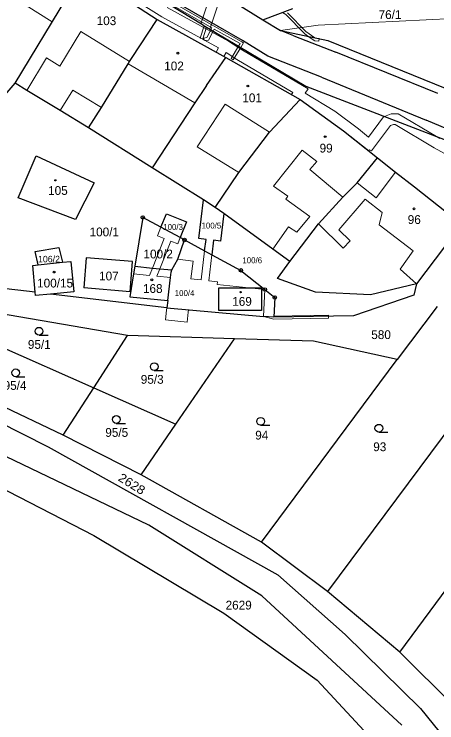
# Model space of a CAD drawing. Extents: x -606517 to -602431, y -1183120 to -1179397.
# Drawn here: x -605326.3 to -605244.5, y -1181147.4 to -1181010.4 of the extents above; entities that cross this region are included whole.
import ezdxf
from ezdxf.enums import TextEntityAlignment as Align

# ---------------------------------------------------------------- set-up
doc = ezdxf.new("R2010")
doc.units = 0
doc.header["$LTSCALE"] = 0.68
for name, color, linetype, lineweight in [('1', 7, 'Continuous', 25), ('13', 7, 'Continuous', 13), ('3', 7, 'Continuous', 25), ('4', 7, 'Continuous', 13), ('5', 7, 'Continuous', 25), ('8', 7, 'Continuous', 25)]:
    doc.layers.add(name, color=color, linetype=linetype, lineweight=lineweight)
doc.layers.add('2', color=7, linetype='Continuous')

msp = doc.modelspace()

# ---------------------------------------------------------------- linework, layer by layer
at = {"layer": '1'}
for p, q in [((-605307.47, -1180993.15), (-605278.18, -1181011.48)), ((-605289.7, -1181012.53), (-605312.8, -1180998.45)), ((-605326.09, -1181023.72), (-605313, -1181002.07)), ((-605313, -1181002.07), (-605298.57, -1181011.41)), ((-605282.12, -1181015.49), (-605296.19, -1181007.32)), ((-605278.18, -1181011.48), (-605272.35, -1181009.31)), ((-605303.57, -1181018.98), (-605298.57, -1181011.41)), ((-605298.57, -1181011.41), (-605285.31, -1181018.79)), ((-605278.18, -1181011.48), (-605274.74, -1181013.56)), ((-605289.7, -1181012.53), (-605269.85, -1181024.33)), ((-605272.13, -1181014.58), (-605274.74, -1181013.56)), ((-605274.74, -1181013.56), (-605265.59, -1181015.49)), ((-605277.19, -1181018.51), (-605282.12, -1181015.49)), ((-605272.13, -1181014.58), (-605264.02, -1181017.75)), ((-605265.59, -1181015.49), (-605242.91, -1181024.7)), ((-605266.78, -1181022.59), (-605277.19, -1181018.51)), ((-605244.28, -1181025.71), (-605264.02, -1181017.75)), ((-605304.2, -1181020.01), (-605303.92, -1181019.55)), ((-605303.92, -1181019.55), (-605303.57, -1181018.98)), ((-605289.08, -1181024.18), (-605285.31, -1181018.79)), ((-605285.31, -1181018.79), (-605270.94, -1181026.88)), ((-605309.38, -1181028.43), (-605304.2, -1181020.01)), ((-605266.78, -1181022.59), (-605246.54, -1181030.86)), ((-605357.02, -1181060.03), (-605326.09, -1181023.72)), ((-605323.82, -1181025.15), (-605326.09, -1181023.72)), ((-605317.36, -1181029.05), (-605323.82, -1181025.15)), ((-605289.08, -1181024.18), (-605291.3, -1181027.55)), ((-605269.85, -1181024.33), (-605225.51, -1181041.42)), ((-605291.3, -1181027.55), (-605299.58, -1181040.1)), ((-605276.84, -1181033.18), (-605270.94, -1181026.88)), ((-605270.94, -1181026.88), (-605262.56, -1181032.95)), ((-605311.91, -1181032.36), (-605317.36, -1181029.05)), ((-605311.91, -1181032.36), (-605309.38, -1181028.43)), ((-605223.86, -1181040.55), (-605246.54, -1181030.86)), ((-605299.58, -1181040.1), (-605311.91, -1181032.36)), ((-605282.8, -1181041.03), (-605276.84, -1181033.18)), ((-605262.56, -1181032.95), (-605255.96, -1181038.18)), ((-605325.5, -1181045.9), (-605322, -1181037.8)), ((-605322, -1181037.8), (-605310.8, -1181043)), ((-605259.92, -1181042.99), (-605255.96, -1181038.18)), ((-605255.96, -1181038.18), (-605252.47, -1181040.91)), ((-605289.64, -1181046.32), (-605299.58, -1181040.1)), ((-605287.36, -1181047.75), (-605282.8, -1181041.03)), ((-605252.47, -1181040.91), (-605248.85, -1181043.75)), ((-605310.8, -1181043), (-605314.4, -1181050.1)), ((-605262.7, -1181045.77), (-605259.92, -1181042.99)), ((-605248.85, -1181043.75), (-605242.6, -1181048.68)), ((-605314.4, -1181050.1), (-605325.5, -1181045.9)), ((-605267.4, -1181050.94), (-605262.7, -1181045.77)), ((-605290.51, -1181053.77), (-605289.64, -1181046.32)), ((-605287.36, -1181047.75), (-605289.64, -1181046.32)), ((-605285.72, -1181048.94), (-605287.36, -1181047.75)), ((-605301.39, -1181049.69), (-605302.91, -1181059.13)), ((-605297.86, -1181051.59), (-605301.39, -1181049.69)), ((-605297.86, -1181051.59), (-605296.81, -1181048.99)), ((-605296.81, -1181048.99), (-605292.92, -1181050.55)), ((-605276.25, -1181055.82), (-605285.72, -1181048.94)), ((-605292.92, -1181050.55), (-605294.14, -1181053.6)), ((-605272.94, -1181058.19), (-605267.4, -1181050.94)), ((-605294.14, -1181053.6), (-605297.86, -1181051.59)), ((-605240.31, -1181051.74), (-605248.45, -1181062.54)), ((-605294.6, -1181057.78), (-605293.3, -1181054.05)), ((-605293.3, -1181054.05), (-605294.14, -1181053.6)), ((-605293.3, -1181054.05), (-605289.41, -1181056.15)), ((-605289.15, -1181053.94), (-605290.51, -1181053.77)), ((-605289.41, -1181056.15), (-605289.15, -1181053.94)), ((-605287.7, -1181054.1), (-605288.02, -1181056.9)), ((-605322.2, -1181056.3), (-605317.6, -1181055.5)), ((-605317.6, -1181055.5), (-605316.9, -1181058.35)), ((-605321.64, -1181058.86), (-605322.2, -1181056.3)), ((-605289.41, -1181056.15), (-605288.02, -1181056.9)), ((-605272.94, -1181058.19), (-605276.25, -1181055.82)), ((-605316.9, -1181058.35), (-605315.31, -1181058.18)), ((-605315.31, -1181058.18), (-605314.71, -1181064.05)), ((-605303.8, -1181064.1), (-605303.4, -1181058.2)), ((-605295.73, -1181059.84), (-605294.6, -1181057.78)), ((-605288.02, -1181056.9), (-605282.4, -1181059.93)), ((-605275.29, -1181061.48), (-605272.94, -1181058.19)), ((-605322.66, -1181058.97), (-605321.64, -1181058.86)), ((-605322.18, -1181064.16), (-605322.66, -1181058.97)), ((-605321.64, -1181058.86), (-605316.9, -1181058.35)), ((-605302.91, -1181059.13), (-605303.15, -1181060.61)), ((-605302.91, -1181059.13), (-605299.5, -1181059.47)), ((-605299.5, -1181059.47), (-605298.09, -1181059.6)), ((-605298.09, -1181059.6), (-605295.73, -1181059.84)), ((-605322.18, -1181064.16), (-605357.02, -1181060.03)), ((-605303.15, -1181060.61), (-605303.86, -1181065.01)), ((-605296.04, -1181061.32), (-605295.92, -1181060.3)), ((-605295.92, -1181060.3), (-605295.73, -1181059.84)), ((-605282.4, -1181059.93), (-605277.77, -1181063.63)), ((-605296.53, -1181065.74), (-605296.04, -1181061.32)), ((-605267.96, -1181064.16), (-605275.29, -1181061.48)), ((-605303.8, -1181064.1), (-605312.8, -1181063.3)), ((-605286.7, -1181063.3), (-605280.85, -1181063.3)), ((-605286.7, -1181067.7), (-605286.7, -1181063.3)), ((-605280.85, -1181063.3), (-605278.4, -1181063.3)), ((-605278.4, -1181063.3), (-605278.4, -1181063.56)), ((-605278.4, -1181063.56), (-605278.4, -1181067.7)), ((-605277.77, -1181063.63), (-605275.85, -1181065.17)), ((-605248.45, -1181062.54), (-605257.33, -1181064.67)), ((-605248.45, -1181062.54), (-605248.94, -1181064.71)), ((-605322.12, -1181064.8), (-605322.18, -1181064.16)), ((-605319.24, -1181064.51), (-605322.12, -1181064.8)), ((-605314.71, -1181064.05), (-605319.24, -1181064.51)), ((-605296.7, -1181067.18), (-605319.24, -1181064.51)), ((-605303.86, -1181065.01), (-605296.53, -1181065.74)), ((-605257.33, -1181064.67), (-605267.96, -1181064.16)), ((-605248.94, -1181064.71), (-605260.6, -1181068.71)), ((-605296.53, -1181065.74), (-605296.7, -1181067.18)), ((-605275.85, -1181065.17), (-605276.05, -1181068.97)), ((-605304.35, -1181072.51), (-605332.24, -1181067.72)), ((-605296.7, -1181067.18), (-605278.05, -1181068.86)), ((-605278.4, -1181067.7), (-605286.7, -1181067.7)), ((-605244.41, -1181066.91), (-605252.17, -1181077.14)), ((-605276.05, -1181068.97), (-605278.05, -1181068.86)), ((-605260.6, -1181068.71), (-605276.05, -1181068.97)), ((-605334.15, -1181072.37), (-605310.87, -1181082.62)), ((-605310.87, -1181082.62), (-605304.35, -1181072.51)), ((-605283.64, -1181073.15), (-605304.35, -1181072.51)), ((-605294.96, -1181089.64), (-605283.64, -1181073.15)), ((-605268.34, -1181073.61), (-605283.64, -1181073.15)), ((-605252.17, -1181077.14), (-605268.34, -1181073.61)), ((-605356.82, -1181075.45), (-605319.69, -1181094.02)), ((-605278.42, -1181112.47), (-605252.17, -1181077.14)), ((-605231.85, -1181076.56), (-605265.64, -1181122.03)), ((-605316.79, -1181091.8), (-605337.96, -1181081.67)), ((-605316.79, -1181091.8), (-605310.87, -1181082.62)), ((-605310.87, -1181082.62), (-605294.96, -1181089.64)), ((-605251.63, -1181133.76), (-605217.59, -1181087.45)), ((-605301.69, -1181099.45), (-605294.96, -1181089.64)), ((-605301.69, -1181099.45), (-605316.79, -1181091.8)), ((-605300.23, -1181109.15), (-605332.19, -1181093.85)), ((-605319.69, -1181094.02), (-605275.27, -1181118.81)), ((-605334.62, -1181098.91), (-605310.86, -1181111.19)), ((-605278.42, -1181112.47), (-605301.69, -1181099.45)), ((-605278.34, -1181122.84), (-605300.23, -1181109.15)), ((-605310.86, -1181111.19), (-605285.73, -1181126.21)), ((-605265.64, -1181122.03), (-605278.42, -1181112.47)), ((-605275.27, -1181118.81), (-605262.26, -1181130.3)), ((-605251.63, -1181133.76), (-605265.64, -1181122.03)), ((-605251.29, -1181147.85), (-605278.34, -1181122.84)), ((-605285.73, -1181126.21), (-605267.62, -1181139.17)), ((-605262.26, -1181130.3), (-605247.67, -1181144.62)), ((-605238.13, -1181147.19), (-605251.63, -1181133.76)), ((-605267.62, -1181139.17), (-605254.57, -1181153.22)), ((-605247.67, -1181144.62), (-605220.34, -1181178.24))]:
    msp.add_line(p, q, dxfattribs=at)
for points in [[(-605285.72, -1181048.94), (-605286.34, -1181054.26), (-605287.7, -1181054.1)], [(-605303.4, -1181058.2), (-605312.3, -1181057.5), (-605312.8, -1181063.3)]]:
    msp.add_lwpolyline(points, dxfattribs=at)
at = {"layer": '13'}
for points in [[(-605299.24, -1181006.56), (-605288, -1181013.05), (-605288.2, -1181013.42), (-605289, -1181014.94), (-605289.58, -1181015.03), (-605289.51, -1181015.52), (-605288.68, -1181015.4), (-605287.77, -1181013.68), (-605287.57, -1181013.29), (-605282.55, -1181016.09), (-605282.86, -1181016.6), (-605284.3, -1181018.98), (-605283.88, -1181019.24), (-605282.43, -1181016.85), (-605281.89, -1181015.96), (-605282.19, -1181015.72), (-605287.55, -1181012.73), (-605298.98, -1181006.12)], [(-605326.18, -1181007.24), (-605318.91, -1181011.85), (-605317.86, -1181010.11)], [(-605304.22, -1181006.8), (-605297.69, -1181010.89), (-605286.73, -1181016.93), (-605287.18, -1181017.75), (-605286.5, -1181018.13), (-605285.71, -1181018.57), (-605285.24, -1181017.82), (-605283.18, -1181019.14), (-605272.33, -1181025.52), (-605272.61, -1181025.94), (-605270.94, -1181026.88), (-605262.56, -1181032.95), (-605257.66, -1181036.83), (-605257.51, -1181036.63), (-605257.12, -1181036.82), (-605253.47, -1181031.94), (-605252.91, -1181031.7), (-605252.56, -1181031.71), (-605244.99, -1181036.22), (-605233.54, -1181042.56)], [(-605243.93, -1181034.46), (-605244.59, -1181034.07), (-605254.63, -1181030.19), (-605254.79, -1181030.26), (-605257.71, -1181034.17), (-605259.64, -1181032.58), (-605264.24, -1181029.17), (-605269.96, -1181025.67), (-605269.41, -1181024.84), (-605282.12, -1181017.38), (-605284.82, -1181015.62), (-605296.65, -1181009.11)], [(-605274.36, -1181010.06), (-605273.72, -1181010.49), (-605270.13, -1181014.16), (-605269.36, -1181014.7), (-605268.09, -1181015.57), (-605267.31, -1181015.62), (-605267.28, -1181015.13), (-605268.09, -1181014.96), (-605269.81, -1181013.78), (-605273.4, -1181010.11)]]:
    msp.add_lwpolyline(points, dxfattribs=at)
for points in [[(-605290.14, -1181012.26), (-605289.7, -1181012.53), (-605288.38, -1181013.31), (-605286.16, -1181006.49), (-605287.9, -1181005.39)], [(-605289.48, -1181012.66), (-605290.26, -1181015.03), (-605289.78, -1181015.19), (-605289.04, -1181012.92)], [(-605254.63, -1181030.19), (-605244.59, -1181034.07), (-605251.98, -1181029.65), (-605253.31, -1181029.64)], [(-605296.96, -1181069.51), (-605292.79, -1181069.96), (-605292.59, -1181067.99), (-605292.55, -1181067.55), (-605296.7, -1181067.18), (-605296.78, -1181067.64)], [(-605276.06, -1181069.37), (-605265.44, -1181069.19), (-605265.45, -1181068.79), (-605265.45, -1181068.59), (-605276.04, -1181068.77), (-605276.05, -1181068.97), (-605278.05, -1181068.86)]]:
    msp.add_lwpolyline(points, close=True, dxfattribs=at)
at = {"layer": '3'}
for p, q in [((-605321.443, -1181072.44), (-605319.693, -1181072.44)), ((-605299.163, -1181079.28), (-605297.413, -1181079.28)), ((-605325.953, -1181080.48), (-605324.203, -1181080.48)), ((-605306.503, -1181089.5), (-605304.753, -1181089.5)), ((-605278.583, -1181089.87), (-605276.833, -1181089.87)), ((-605255.713, -1181091.19), (-605253.963, -1181091.19))]:
    msp.add_line(p, q, dxfattribs=at)
for centre in [(-605321.4429, -1181071.6898), (-605299.1629, -1181078.5298), (-605325.9529, -1181079.7298), (-605306.5029, -1181088.7498), (-605278.5829, -1181089.1198), (-605255.7129, -1181090.4398)]:
    msp.add_circle(centre, 0.75, dxfattribs=at)
at = {"layer": '4'}
for p, q in [((-605236.55, -1181010.99), (-605267.44, -1181012.5)), ((-605267.44, -1181012.5), (-605274.74, -1181013.56)), ((-605313.37, -1181013.77), (-605317.4, -1181020.43)), ((-605303.92, -1181019.55), (-605313.37, -1181013.77)), ((-605320.02, -1181018.85), (-605323.82, -1181025.15)), ((-605317.4, -1181020.43), (-605320.02, -1181018.85)), ((-605291.3, -1181027.55), (-605304.2, -1181020.01)), ((-605314.89, -1181025.06), (-605317.36, -1181029.05)), ((-605309.38, -1181028.43), (-605314.89, -1181025.06)), ((-605285.46, -1181027.78), (-605290.86, -1181036.03)), ((-605278.26, -1181032.3), (-605285.46, -1181027.78)), ((-605276.84, -1181033.18), (-605278.26, -1181032.3)), ((-605290.86, -1181036.03), (-605282.8, -1181041.03)), ((-605270.55, -1181036.7), (-605276.12, -1181043.62)), ((-605267.72, -1181038.85), (-605270.55, -1181036.7)), ((-605269.05, -1181040.45), (-605267.72, -1181038.85)), ((-605262.7, -1181045.77), (-605269.05, -1181040.45)), ((-605256.25, -1181045.93), (-605252.47, -1181040.91)), ((-605259.92, -1181042.99), (-605256.25, -1181045.93)), ((-605276.12, -1181043.62), (-605273.35, -1181045.6)), ((-605273.35, -1181045.6), (-605273.74, -1181046.15)), ((-605273.74, -1181046.15), (-605269.06, -1181049.49)), ((-605258.34, -1181046.13), (-605263.43, -1181052.1)), ((-605255.08, -1181048.77), (-605258.34, -1181046.13)), ((-605269.06, -1181049.49), (-605271.6, -1181052.51)), ((-605255.68, -1181051.13), (-605255.08, -1181048.77)), ((-605262.59, -1181055.62), (-605267.4, -1181050.94)), ((-605249.05, -1181056.16), (-605255.68, -1181051.13)), ((-605298.53, -1181053.24), (-605297.86, -1181051.59)), ((-605273.18, -1181051.5), (-605276.25, -1181055.82)), ((-605271.6, -1181052.51), (-605273.18, -1181051.5)), ((-605263.43, -1181052.1), (-605261.26, -1181054.19)), ((-605299.5, -1181059.47), (-605297.23, -1181053.77)), ((-605297.23, -1181053.77), (-605298.53, -1181053.24)), ((-605294.14, -1181053.6), (-605294.63, -1181054.81)), ((-605295.93, -1181054.29), (-605298.09, -1181059.6)), ((-605294.63, -1181054.81), (-605295.93, -1181054.29)), ((-605261.26, -1181054.19), (-605262.59, -1181055.62)), ((-605290.06, -1181061.78), (-605289.41, -1181056.15)), ((-605251.57, -1181059.67), (-605249.05, -1181056.16)), ((-605294.6, -1181057.78), (-605291.61, -1181058.13)), ((-605291.61, -1181058.13), (-605292.07, -1181061.55)), ((-605288.02, -1181056.9), (-605288.61, -1181061.95)), ((-605300.08, -1181060.92), (-605299.5, -1181059.47)), ((-605298.09, -1181059.6), (-605298.68, -1181061.05)), ((-605303.15, -1181060.61), (-605300.08, -1181060.92)), ((-605248.45, -1181062.54), (-605251.57, -1181059.67)), ((-605298.68, -1181061.05), (-605296.04, -1181061.32)), ((-605292.07, -1181061.55), (-605290.06, -1181061.78)), ((-605288.61, -1181061.95), (-605286.95, -1181062.15)), ((-605286.95, -1181062.15), (-605287.01, -1181062.64)), ((-605287.01, -1181062.64), (-605280.85, -1181063.3)), ((-605280.85, -1181063.3), (-605278.4, -1181063.56)), ((-605278.4, -1181063.56), (-605277.77, -1181063.63)), ((-605277.77, -1181063.63), (-605278.05, -1181068.86))]:
    msp.add_line(p, q, dxfattribs=at)
at = {"layer": '5'}
for centre, radius in [((-605294.5768, -1181017.9292), 0.175), ((-605281.0368, -1181024.2892), 0.175), ((-605266.0968, -1181034.0792), 0.175), ((-605318.2846, -1181042.5194), 0.1172), ((-605248.9168, -1181048.0292), 0.175), ((-605318.5168, -1181060.2492), 0.175), ((-605299.6368, -1181061.7592), 0.175), ((-605282.4646, -1181064.1494), 0.1172)]:
    msp.add_circle(centre, radius, dxfattribs=at)
at = {"layer": '8'}
for centre, radius in [((-605301.39, -1181049.6899), 0.335), ((-605301.39, -1181049.6899), 0.0203), ((-605293.3, -1181054.0499), 0.335), ((-605293.3, -1181054.0499), 0.0203), ((-605282.4, -1181059.9299), 0.335), ((-605282.4, -1181059.9299), 0.0203), ((-605277.77, -1181063.6299), 0.335), ((-605277.77, -1181063.6299), 0.0203), ((-605275.85, -1181065.1699), 0.335), ((-605275.85, -1181065.1699), 0.0203)]:
    msp.add_circle(centre, radius, dxfattribs=at)

# ---------------------------------------------------------------- texts
at = {"layer": '2'}
for s, height, p in [('76/1', 1.7, (-605255.77, -1181011.335)), ('103', 1.7, (-605310.3, -1181012.515)), ('101', 1.7, (-605282.13, -1181027.415)), ('99', 1.7, (-605267.18, -1181037.145)), ('105', 1.7, (-605319.69, -1181045.335)), ('96', 1.7, (-605250.13, -1181050.955)), ('100/1', 1.7, (-605311.67, -1181053.345)), ('100/2', 1.7, (-605301.25, -1181057.615)), ('106/2', 1.27, (-605321.65, -1181058.387)), ('100/15', 1.7, (-605321.82, -1181063.235)), ('168', 1.7, (-605301.35, -1181064.285)), ('169', 1.7, (-605284.08, -1181066.775)), ('95/1', 1.7, (-605323.61, -1181075.095)), ('95/3', 1.7, (-605301.77, -1181081.845)), ('95/4', 1.7, (-605328.3, -1181083.025)), ('95/5', 1.7, (-605308.63, -1181092.105)), ('94', 1.7, (-605279.63, -1181092.635)), ('93', 1.7, (-605256.8, -1181094.875)), ('2629', 1.7, (-605285.36, -1181125.485))]:
    msp.add_text(s, height=height, dxfattribs=at).set_placement(p)
for s, height, p in [('102', 1.7, (-605295.339, -1181021.265)), ('100/3', 1.14, (-605295.519, -1181052.1)), ('100/5', 1.14, (-605288.109, -1181051.83)), ('100/6', 1.14, (-605280.209, -1181058.55)), ('107', 1.7, (-605307.939, -1181061.865)), ('100/4', 1.14, (-605293.289, -1181064.88)), ('580', 1.7, (-605255.289, -1181073.205))]:
    msp.add_text(s, height=height, dxfattribs=at).set_placement(p, align=Align.CENTER)
at = {"layer": '2', "width": 1.1}
msp.add_text('2628', height=1.7, rotation=328, dxfattribs=at).set_placement((-605306.305, -1181100.45))

doc.saveas('drawing.dxf')
